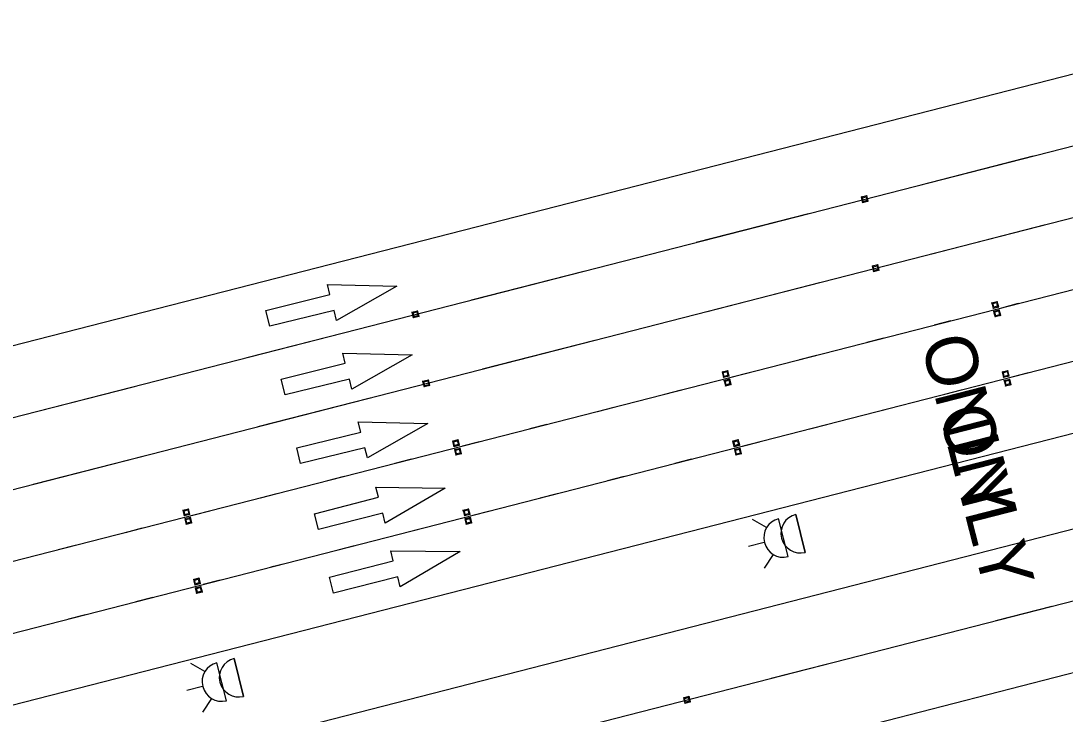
# Model space of a CAD drawing. Extents: x 2471014 to 2497726, y 6959577 to 6980268.
# Drawn here: x 2485375.6 to 2485555.7, y 6968012 to 6968131.5 of the extents above; entities that cross this region are included whole.
import ezdxf

# ---------------------------------------------------------------- set-up
doc = ezdxf.new("R2010")
doc.units = 0
for name, color, linetype in [('1', 7, 'Continuous'), ('13', 7, 'Continuous'), ('18', 7, 'Continuous'), ('23', 7, 'Continuous'), ('5', 7, 'Continuous'), ('59', 7, 'Continuous'), ('ALIGN_ML_IH35_NB_SB', 7, 'Continuous'), ('C-ANNO-NOTE', 7, 'Continuous'), ('C-COMM-IDEN', 7, 'Continuous'), ('Level 40', 7, 'Continuous'), ('p_structure fence', 7, 'Continuous'), ('RDWY_PAVE_XSTREET_FOC', 7, 'Continuous'), ('V7_25', 7, 'Continuous')]:
    doc.layers.add(name, color=color, linetype=linetype)

msp = doc.modelspace()

# ---------------------------------------------------------------- linework, layer by layer
at = {"layer": '1'}
for p, q in [((2485543.74, 6968028.09), (2485553.42, 6968030.57)), ((2485504.99, 6968018.16), (2485514.68, 6968020.64))]:
    msp.add_line(p, q, dxfattribs=at)
at = {"layer": '13'}
for p, q in [((2485091.11, 6967924.47), (2486403.87, 6968260.92)), ((2484238.76, 6967784.48), (2485861.87, 6968200.47))]:
    msp.add_line(p, q, dxfattribs=at)
at = {"layer": '18'}
for p, q in [((2485097.06, 6967901.22), (2486409.83, 6968237.67)), ((2484287.61, 6967735.06), (2485876.76, 6968142.35))]:
    msp.add_line(p, q, dxfattribs=at)
at = {"layer": '23'}
for p, q in [((2485520.51, 6968101.11), (2485521.49, 6968101.36)), ((2485520.71, 6968100.99), (2485520.51, 6968101.11)), ((2485520.51, 6968101.11), (2485520.58, 6968100.85)), ((2485520.58, 6968100.85), (2485520.76, 6968100.12)), ((2485520.88, 6968100.34), (2485520.71, 6968100.99)), ((2485521.49, 6968101.36), (2485521.37, 6968101.16)), ((2485521.37, 6968101.16), (2485521.4, 6968101.02)), ((2485521.4, 6968101.02), (2485521.54, 6968100.51)), ((2485521.74, 6968100.38), (2485521.49, 6968101.36)), ((2485521.54, 6968100.51), (2485521.74, 6968100.38)), ((2485521.74, 6968100.38), (2485520.76, 6968100.12)), ((2485520.76, 6968100.12), (2485520.88, 6968100.34)), ((2485522.38, 6968089.22), (2485523.36, 6968089.47)), ((2485522.59, 6968089.09), (2485522.38, 6968089.22)), ((2485522.38, 6968089.22), (2485522.63, 6968088.23)), ((2485522.72, 6968088.57), (2485522.59, 6968089.09)), ((2485523.61, 6968088.49), (2485522.63, 6968088.23)), ((2485522.63, 6968088.23), (2485522.75, 6968088.43)), ((2485522.75, 6968088.43), (2485522.72, 6968088.57)), ((2485523.36, 6968089.47), (2485523.24, 6968089.26)), ((2485523.24, 6968089.26), (2485523.41, 6968088.6)), ((2485523.55, 6968088.75), (2485523.36, 6968089.47)), ((2485523.41, 6968088.6), (2485523.61, 6968088.49)), ((2485523.61, 6968088.49), (2485523.55, 6968088.75)), ((2485543.01, 6968082.87), (2485543.99, 6968083.12)), ((2485543.21, 6968082.76), (2485543.01, 6968082.87)), ((2485543.01, 6968082.87), (2485543.08, 6968082.61)), ((2485543.08, 6968082.61), (2485543.26, 6968081.89)), ((2485543.38, 6968082.1), (2485543.21, 6968082.76)), ((2485543.99, 6968083.12), (2485543.87, 6968082.93)), ((2485543.87, 6968082.93), (2485543.9, 6968082.79)), ((2485543.9, 6968082.79), (2485544.04, 6968082.27)), ((2485544.24, 6968082.14), (2485543.99, 6968083.12)), ((2485443.02, 6968081.24), (2485444, 6968081.5)), ((2485443.22, 6968081.13), (2485443.02, 6968081.24)), ((2485443.02, 6968081.24), (2485443.08, 6968080.98)), ((2485443.08, 6968080.98), (2485443.27, 6968080.26)), ((2485443.39, 6968080.48), (2485443.22, 6968081.13)), ((2485444, 6968081.5), (2485443.87, 6968081.3)), ((2485443.87, 6968081.3), (2485443.91, 6968081.16)), ((2485443.91, 6968081.16), (2485444.04, 6968080.64)), ((2485444.25, 6968080.51), (2485444, 6968081.5)), ((2485444.04, 6968080.64), (2485444.25, 6968080.51)), ((2485544.24, 6968082.14), (2485543.26, 6968081.89)), ((2485543.26, 6968081.89), (2485543.38, 6968082.1)), ((2485543.34, 6968081.41), (2485544.33, 6968081.66)), ((2485543.54, 6968081.29), (2485543.34, 6968081.41)), ((2485543.34, 6968081.41), (2485543.41, 6968081.15)), ((2485543.41, 6968081.15), (2485543.59, 6968080.43)), ((2485543.71, 6968080.64), (2485543.54, 6968081.29)), ((2485544.58, 6968080.68), (2485543.59, 6968080.43)), ((2485543.59, 6968080.43), (2485543.71, 6968080.64)), ((2485544.04, 6968082.27), (2485544.24, 6968082.14)), ((2485544.33, 6968081.66), (2485544.2, 6968081.46)), ((2485544.2, 6968081.46), (2485544.24, 6968081.33)), ((2485544.24, 6968081.33), (2485544.37, 6968080.81)), ((2485544.58, 6968080.68), (2485544.33, 6968081.66)), ((2485544.37, 6968080.81), (2485544.58, 6968080.68)), ((2485444.25, 6968080.51), (2485443.27, 6968080.26)), ((2485443.27, 6968080.26), (2485443.39, 6968080.48)), ((2485496.51, 6968070.95), (2485497.5, 6968071.21)), ((2485496.72, 6968070.84), (2485496.51, 6968070.95)), ((2485496.51, 6968070.95), (2485496.58, 6968070.69)), ((2485496.58, 6968070.69), (2485496.76, 6968069.97)), ((2485496.88, 6968070.19), (2485496.72, 6968070.84)), ((2485497.75, 6968070.22), (2485496.76, 6968069.97)), ((2485496.76, 6968069.97), (2485496.88, 6968070.19)), ((2485497.5, 6968071.21), (2485497.37, 6968071.01)), ((2485497.37, 6968071.01), (2485497.41, 6968070.87)), ((2485497.41, 6968070.87), (2485497.54, 6968070.35)), ((2485497.75, 6968070.22), (2485497.5, 6968071.21)), ((2485497.54, 6968070.35), (2485497.75, 6968070.22)), ((2485544.82, 6968070.95), (2485545.81, 6968071.2)), ((2485545.03, 6968070.83), (2485544.82, 6968070.95)), ((2485544.82, 6968070.95), (2485544.89, 6968070.69)), ((2485544.89, 6968070.69), (2485545.08, 6968069.97)), ((2485545.19, 6968070.18), (2485545.03, 6968070.83)), ((2485546.06, 6968070.22), (2485545.08, 6968069.97)), ((2485545.08, 6968069.97), (2485545.19, 6968070.18)), ((2485545.81, 6968071.2), (2485545.68, 6968071)), ((2485545.68, 6968071), (2485545.72, 6968070.87)), ((2485545.72, 6968070.87), (2485545.85, 6968070.35)), ((2485546.06, 6968070.22), (2485545.81, 6968071.2)), ((2485545.85, 6968070.35), (2485546.06, 6968070.22)), ((2485444.88, 6968069.36), (2485445.87, 6968069.61)), ((2485445.09, 6968069.23), (2485444.88, 6968069.36)), ((2485444.88, 6968069.36), (2485445.13, 6968068.37)), ((2485445.22, 6968068.71), (2485445.09, 6968069.23)), ((2485446.12, 6968068.63), (2485445.13, 6968068.37)), ((2485445.13, 6968068.37), (2485445.26, 6968068.57)), ((2485445.26, 6968068.57), (2485445.22, 6968068.71)), ((2485445.87, 6968069.61), (2485445.75, 6968069.39)), ((2485445.75, 6968069.39), (2485445.92, 6968068.74)), ((2485446.05, 6968068.89), (2485445.87, 6968069.61)), ((2485445.92, 6968068.74), (2485446.12, 6968068.63)), ((2485446.12, 6968068.63), (2485446.05, 6968068.89)), ((2485496.85, 6968069.49), (2485497.83, 6968069.74)), ((2485497.05, 6968069.38), (2485496.85, 6968069.49)), ((2485496.85, 6968069.49), (2485496.91, 6968069.23)), ((2485496.91, 6968069.23), (2485497.1, 6968068.51)), ((2485497.22, 6968068.72), (2485497.05, 6968069.38)), ((2485498.08, 6968068.76), (2485497.1, 6968068.51)), ((2485497.1, 6968068.51), (2485497.22, 6968068.72)), ((2485497.83, 6968069.74), (2485497.7, 6968069.55)), ((2485497.7, 6968069.55), (2485497.74, 6968069.41)), ((2485497.74, 6968069.41), (2485497.87, 6968068.89)), ((2485498.08, 6968068.76), (2485497.83, 6968069.74)), ((2485497.87, 6968068.89), (2485498.08, 6968068.76)), ((2485545.14, 6968069.48), (2485546.13, 6968069.73)), ((2485545.35, 6968069.37), (2485545.14, 6968069.48)), ((2485545.14, 6968069.48), (2485545.21, 6968069.22)), ((2485545.21, 6968069.22), (2485545.4, 6968068.5)), ((2485545.51, 6968068.71), (2485545.35, 6968069.37)), ((2485546.38, 6968068.75), (2485545.4, 6968068.5)), ((2485545.4, 6968068.5), (2485545.51, 6968068.71)), ((2485546.13, 6968069.73), (2485546, 6968069.54)), ((2485546, 6968069.54), (2485546.04, 6968069.4)), ((2485546.04, 6968069.4), (2485546.17, 6968068.88)), ((2485546.38, 6968068.75), (2485546.13, 6968069.73)), ((2485546.17, 6968068.88), (2485546.38, 6968068.75)), ((2485450.02, 6968059.04), (2485451, 6968059.29)), ((2485450.22, 6968058.92), (2485450.02, 6968059.04)), ((2485450.02, 6968059.04), (2485450.08, 6968058.78)), ((2485451, 6968059.29), (2485450.87, 6968059.09)), ((2485450.87, 6968059.09), (2485450.91, 6968058.96)), ((2485451.25, 6968058.31), (2485451, 6968059.29)), ((2485498.33, 6968059.03), (2485499.31, 6968059.28)), ((2485498.53, 6968058.92), (2485498.33, 6968059.03)), ((2485498.33, 6968059.03), (2485498.39, 6968058.77)), ((2485499.31, 6968059.28), (2485499.18, 6968059.09)), ((2485499.18, 6968059.09), (2485499.22, 6968058.95)), ((2485499.56, 6968058.3), (2485499.31, 6968059.28)), ((2485450.08, 6968058.78), (2485450.27, 6968058.06)), ((2485450.39, 6968058.27), (2485450.22, 6968058.92)), ((2485451.25, 6968058.31), (2485450.27, 6968058.06)), ((2485450.27, 6968058.06), (2485450.39, 6968058.27)), ((2485450.35, 6968057.57), (2485451.33, 6968057.83)), ((2485450.55, 6968057.46), (2485450.35, 6968057.57)), ((2485450.35, 6968057.57), (2485450.41, 6968057.31)), ((2485450.41, 6968057.31), (2485450.6, 6968056.59)), ((2485450.72, 6968056.81), (2485450.55, 6968057.46)), ((2485450.91, 6968058.96), (2485451.04, 6968058.44)), ((2485451.04, 6968058.44), (2485451.25, 6968058.31)), ((2485451.33, 6968057.83), (2485451.21, 6968057.63)), ((2485451.21, 6968057.63), (2485451.24, 6968057.49)), ((2485451.24, 6968057.49), (2485451.37, 6968056.97)), ((2485451.58, 6968056.84), (2485451.33, 6968057.83)), ((2485498.39, 6968058.77), (2485498.58, 6968058.05)), ((2485498.7, 6968058.26), (2485498.53, 6968058.92)), ((2485499.56, 6968058.3), (2485498.58, 6968058.05)), ((2485498.58, 6968058.05), (2485498.7, 6968058.26)), ((2485498.65, 6968057.56), (2485499.63, 6968057.82)), ((2485498.85, 6968057.45), (2485498.65, 6968057.56)), ((2485498.65, 6968057.56), (2485498.71, 6968057.3)), ((2485498.71, 6968057.3), (2485498.9, 6968056.58)), ((2485499.02, 6968056.8), (2485498.85, 6968057.45)), ((2485499.22, 6968058.95), (2485499.35, 6968058.43)), ((2485499.35, 6968058.43), (2485499.56, 6968058.3)), ((2485499.63, 6968057.82), (2485499.5, 6968057.62)), ((2485499.5, 6968057.62), (2485499.54, 6968057.48)), ((2485499.54, 6968057.48), (2485499.67, 6968056.96)), ((2485499.88, 6968056.83), (2485499.63, 6968057.82)), ((2485451.58, 6968056.84), (2485450.6, 6968056.59)), ((2485450.6, 6968056.59), (2485450.72, 6968056.81)), ((2485451.37, 6968056.97), (2485451.58, 6968056.84)), ((2485499.88, 6968056.83), (2485498.9, 6968056.58)), ((2485498.9, 6968056.58), (2485499.02, 6968056.8)), ((2485499.67, 6968056.96), (2485499.88, 6968056.83)), ((2485403.52, 6968047.12), (2485404.5, 6968047.37)), ((2485403.72, 6968047.01), (2485403.52, 6968047.12)), ((2485403.52, 6968047.12), (2485403.59, 6968046.86)), ((2485403.59, 6968046.86), (2485403.77, 6968046.14)), ((2485403.89, 6968046.35), (2485403.72, 6968047.01)), ((2485404.5, 6968047.37), (2485404.38, 6968047.18)), ((2485404.38, 6968047.18), (2485404.41, 6968047.04)), ((2485404.41, 6968047.04), (2485404.55, 6968046.52)), ((2485404.75, 6968046.39), (2485404.5, 6968047.37)), ((2485404.55, 6968046.52), (2485404.75, 6968046.39)), ((2485451.83, 6968047.11), (2485452.81, 6968047.37)), ((2485452.03, 6968047), (2485451.83, 6968047.11)), ((2485451.83, 6968047.11), (2485451.9, 6968046.85)), ((2485451.9, 6968046.85), (2485452.08, 6968046.13)), ((2485452.2, 6968046.35), (2485452.03, 6968047)), ((2485452.81, 6968047.37), (2485452.69, 6968047.17)), ((2485452.69, 6968047.17), (2485452.72, 6968047.03)), ((2485452.72, 6968047.03), (2485452.85, 6968046.51)), ((2485453.06, 6968046.38), (2485452.81, 6968047.37)), ((2485452.85, 6968046.51), (2485453.06, 6968046.38)), ((2485404.75, 6968046.39), (2485403.77, 6968046.14)), ((2485403.77, 6968046.14), (2485403.89, 6968046.35)), ((2485403.85, 6968045.66), (2485404.83, 6968045.91)), ((2485404.05, 6968045.54), (2485403.85, 6968045.66)), ((2485403.85, 6968045.66), (2485403.92, 6968045.4)), ((2485403.92, 6968045.4), (2485404.1, 6968044.68)), ((2485404.22, 6968044.89), (2485404.05, 6968045.54)), ((2485405.08, 6968044.93), (2485404.1, 6968044.68)), ((2485404.1, 6968044.68), (2485404.22, 6968044.89)), ((2485404.83, 6968045.91), (2485404.71, 6968045.71)), ((2485404.71, 6968045.71), (2485404.74, 6968045.58)), ((2485404.74, 6968045.58), (2485404.88, 6968045.06)), ((2485405.08, 6968044.93), (2485404.83, 6968045.91)), ((2485404.88, 6968045.06), (2485405.08, 6968044.93)), ((2485453.06, 6968046.38), (2485452.08, 6968046.13)), ((2485452.08, 6968046.13), (2485452.2, 6968046.35)), ((2485452.15, 6968045.65), (2485453.13, 6968045.9)), ((2485452.35, 6968045.53), (2485452.15, 6968045.65)), ((2485452.15, 6968045.65), (2485452.22, 6968045.39)), ((2485452.22, 6968045.39), (2485452.4, 6968044.67)), ((2485452.52, 6968044.88), (2485452.35, 6968045.53)), ((2485453.38, 6968044.92), (2485452.4, 6968044.67)), ((2485452.4, 6968044.67), (2485452.52, 6968044.88)), ((2485453.13, 6968045.9), (2485453.01, 6968045.7)), ((2485453.01, 6968045.7), (2485453.04, 6968045.57)), ((2485453.04, 6968045.57), (2485453.17, 6968045.05)), ((2485453.38, 6968044.92), (2485453.13, 6968045.9)), ((2485453.17, 6968045.05), (2485453.38, 6968044.92)), ((2485405.33, 6968035.2), (2485406.32, 6968035.45)), ((2485405.53, 6968035.08), (2485405.33, 6968035.2)), ((2485405.33, 6968035.2), (2485405.4, 6968034.94)), ((2485405.4, 6968034.94), (2485405.58, 6968034.22)), ((2485405.7, 6968034.43), (2485405.53, 6968035.08)), ((2485406.57, 6968034.47), (2485405.58, 6968034.22)), ((2485405.58, 6968034.22), (2485405.7, 6968034.43)), ((2485405.65, 6968033.73), (2485406.63, 6968033.98)), ((2485406.32, 6968035.45), (2485406.19, 6968035.25)), ((2485406.19, 6968035.25), (2485406.22, 6968035.12)), ((2485406.22, 6968035.12), (2485406.36, 6968034.6)), ((2485406.57, 6968034.47), (2485406.32, 6968035.45)), ((2485406.36, 6968034.6), (2485406.57, 6968034.47)), ((2485406.63, 6968033.98), (2485406.51, 6968033.79)), ((2485406.88, 6968033), (2485406.63, 6968033.98)), ((2485405.85, 6968033.62), (2485405.65, 6968033.73)), ((2485405.65, 6968033.73), (2485405.72, 6968033.47)), ((2485405.72, 6968033.47), (2485405.9, 6968032.75)), ((2485406.02, 6968032.96), (2485405.85, 6968033.62)), ((2485406.88, 6968033), (2485405.9, 6968032.75)), ((2485405.9, 6968032.75), (2485406.02, 6968032.96)), ((2485406.51, 6968033.79), (2485406.54, 6968033.65)), ((2485406.54, 6968033.65), (2485406.68, 6968033.13)), ((2485406.68, 6968033.13), (2485406.88, 6968033)), ((2485489.84, 6968014.79), (2485490.83, 6968015.04)), ((2485490.05, 6968014.68), (2485489.84, 6968014.79)), ((2485489.84, 6968014.79), (2485489.91, 6968014.53)), ((2485489.91, 6968014.53), (2485490.1, 6968013.81)), ((2485490.21, 6968014.02), (2485490.05, 6968014.68)), ((2485491.08, 6968014.06), (2485490.1, 6968013.81)), ((2485490.1, 6968013.81), (2485490.21, 6968014.02)), ((2485490.83, 6968015.04), (2485490.7, 6968014.85)), ((2485490.7, 6968014.85), (2485490.74, 6968014.71)), ((2485490.74, 6968014.71), (2485490.87, 6968014.19)), ((2485491.08, 6968014.06), (2485490.83, 6968015.04)), ((2485490.87, 6968014.19), (2485491.08, 6968014.06))]:
    msp.add_line(p, q, dxfattribs=at)
for points in [[(2485520.71, 6968100.99), (2485521.37, 6968101.16), (2485521.54, 6968100.51), (2485520.88, 6968100.34)], [(2485523.41, 6968088.6), (2485522.75, 6968088.43), (2485522.59, 6968089.09), (2485523.24, 6968089.26)], [(2485543.21, 6968082.76), (2485543.87, 6968082.93), (2485544.04, 6968082.27), (2485543.38, 6968082.1)], [(2485443.22, 6968081.13), (2485443.87, 6968081.3), (2485444.04, 6968080.64), (2485443.39, 6968080.48)], [(2485543.54, 6968081.29), (2485544.2, 6968081.46), (2485544.37, 6968080.81), (2485543.71, 6968080.64)], [(2485496.72, 6968070.84), (2485497.37, 6968071.01), (2485497.54, 6968070.35), (2485496.88, 6968070.19)], [(2485545.03, 6968070.83), (2485545.68, 6968071), (2485545.85, 6968070.35), (2485545.19, 6968070.18)], [(2485445.92, 6968068.74), (2485445.26, 6968068.57), (2485445.09, 6968069.23), (2485445.75, 6968069.39)], [(2485497.05, 6968069.38), (2485497.7, 6968069.55), (2485497.87, 6968068.89), (2485497.22, 6968068.72)], [(2485545.35, 6968069.37), (2485546, 6968069.54), (2485546.17, 6968068.88), (2485545.51, 6968068.71)], [(2485450.22, 6968058.92), (2485450.87, 6968059.09), (2485451.04, 6968058.44), (2485450.39, 6968058.27)], [(2485498.53, 6968058.92), (2485499.18, 6968059.09), (2485499.35, 6968058.43), (2485498.7, 6968058.26)], [(2485450.55, 6968057.46), (2485451.21, 6968057.63), (2485451.37, 6968056.97), (2485450.72, 6968056.81)], [(2485498.85, 6968057.45), (2485499.5, 6968057.62), (2485499.67, 6968056.96), (2485499.02, 6968056.8)], [(2485403.72, 6968047.01), (2485404.38, 6968047.18), (2485404.55, 6968046.52), (2485403.89, 6968046.35)], [(2485452.03, 6968047), (2485452.69, 6968047.17), (2485452.85, 6968046.51), (2485452.2, 6968046.35)], [(2485404.05, 6968045.54), (2485404.71, 6968045.71), (2485404.88, 6968045.06), (2485404.22, 6968044.89)], [(2485452.35, 6968045.53), (2485453.01, 6968045.7), (2485453.17, 6968045.05), (2485452.52, 6968044.88)], [(2485405.53, 6968035.08), (2485406.19, 6968035.25), (2485406.36, 6968034.6), (2485405.7, 6968034.43)], [(2485405.85, 6968033.62), (2485406.51, 6968033.79), (2485406.68, 6968033.13), (2485406.02, 6968032.96)], [(2485490.05, 6968014.68), (2485490.7, 6968014.85), (2485490.87, 6968014.19), (2485490.21, 6968014.02)]]:
    msp.add_lwpolyline(points, close=True, dxfattribs=at)
at = {"layer": '5'}
msp.add_arc((2479474.04, 6969335.88), 8460, 6.37617, 6.37617, dxfattribs=at)
at = {"layer": '59'}
for p, q in [((2484247.64, 6967749.59), (2485580.2, 6968091.11)), ((2484442.23, 6967787.08), (2485583.18, 6968079.49))]:
    msp.add_line(p, q, dxfattribs=at)
at = {"layer": 'ALIGN_ML_IH35_NB_SB'}
for p, q in [((2485428.87, 6968084.28), (2485428.44, 6968086.03)), ((2485428.44, 6968086.03), (2485440.43, 6968085.76)), ((2485417.82, 6968081.57), (2485428.87, 6968084.28)), ((2485440.43, 6968085.76), (2485430.02, 6968079.81)), ((2485418.5, 6968078.83), (2485417.82, 6968081.57)), ((2485429.6, 6968081.56), (2485418.5, 6968078.83)), ((2485430.02, 6968079.81), (2485429.6, 6968081.56)), ((2485431.53, 6968072.44), (2485431.1, 6968074.19)), ((2485431.1, 6968074.19), (2485443.09, 6968073.92)), ((2485443.09, 6968073.92), (2485432.69, 6968067.96)), ((2485420.48, 6968069.73), (2485431.53, 6968072.44)), ((2485421.16, 6968066.99), (2485420.48, 6968069.73)), ((2485432.26, 6968069.71), (2485421.16, 6968066.99)), ((2485432.69, 6968067.96), (2485432.26, 6968069.71)), ((2485434.19, 6968060.59), (2485433.76, 6968062.34)), ((2485433.76, 6968062.34), (2485445.75, 6968062.07)), ((2485445.75, 6968062.07), (2485435.35, 6968056.12)), ((2485423.15, 6968057.88), (2485434.19, 6968060.59)), ((2485423.82, 6968055.14), (2485423.15, 6968057.88)), ((2485434.92, 6968057.87), (2485423.82, 6968055.14)), ((2485435.35, 6968056.12), (2485434.92, 6968057.87)), ((2485437.24, 6968049.34), (2485436.79, 6968051.08)), ((2485436.79, 6968051.08), (2485448.78, 6968050.93)), ((2485448.78, 6968050.93), (2485438.44, 6968044.88)), ((2485426.22, 6968046.51), (2485437.24, 6968049.34)), ((2485426.92, 6968043.78), (2485426.22, 6968046.51)), ((2485438, 6968046.62), (2485426.92, 6968043.78)), ((2485438.44, 6968044.88), (2485438, 6968046.62)), ((2485439.82, 6968038.37), (2485439.37, 6968040.12)), ((2485439.37, 6968040.12), (2485451.36, 6968039.97)), ((2485451.36, 6968039.97), (2485441.02, 6968033.91)), ((2485428.81, 6968035.55), (2485439.82, 6968038.37)), ((2485440.58, 6968035.66), (2485429.51, 6968032.82)), ((2485441.02, 6968033.91), (2485440.58, 6968035.66)), ((2485429.51, 6968032.82), (2485428.81, 6968035.55))]:
    msp.add_line(p, q, dxfattribs=at)
at = {"layer": 'C-ANNO-NOTE'}
msp.add_line((2485094.03, 6967912.83), (2486406.85, 6968249.3), dxfattribs=at)
at = {"layer": 'C-COMM-IDEN'}
for p, q in [((2485504.18, 6968044.12), (2485501.75, 6968045.53)), ((2485507.89, 6968039.11), (2485506.26, 6968045.66)), ((2485509.22, 6968046.4), (2485510.86, 6968039.85)), ((2485510.86, 6968039.85), (2485509.22, 6968046.4)), ((2485503.8, 6968041.56), (2485501.07, 6968040.88)), ((2485505.34, 6968039.49), (2485503.8, 6968037.13)), ((2485412.36, 6968021.57), (2485413.99, 6968015.02)), ((2485413.99, 6968015.02), (2485412.36, 6968021.57)), ((2485407.31, 6968019.29), (2485404.88, 6968020.71)), ((2485411.03, 6968014.28), (2485409.39, 6968020.83)), ((2485406.93, 6968016.74), (2485404.2, 6968016.06)), ((2485408.47, 6968014.66), (2485406.93, 6968012.31))]:
    msp.add_line(p, q, dxfattribs=at)
for centre in [(2485507.08, 6968042.38), (2485510.04, 6968043.12), (2485413.17, 6968018.29), (2485410.21, 6968017.55)]:
    msp.add_arc(centre, 3.37, 104.0161, 284.0161, dxfattribs=at)
at = {"layer": 'Level 40'}
for p, q in [((2485544.76, 6968082.03), (2485547.66, 6968082.78)), ((2485533.13, 6968079.05), (2485536.04, 6968079.8)), ((2485521.51, 6968076.07), (2485524.41, 6968076.82)), ((2485509.88, 6968073.09), (2485512.79, 6968073.84)), ((2485498.26, 6968070.11), (2485501.17, 6968070.86)), ((2485546.54, 6968070.1), (2485549.45, 6968070.84)), ((2485486.64, 6968067.13), (2485489.54, 6968067.88)), ((2485534.92, 6968067.12), (2485537.82, 6968067.87)), ((2485475.01, 6968064.16), (2485477.92, 6968064.9)), ((2485523.29, 6968064.14), (2485526.2, 6968064.89)), ((2485463.39, 6968061.18), (2485466.29, 6968061.92)), ((2485511.67, 6968061.16), (2485514.57, 6968061.91)), ((2485451.76, 6968058.2), (2485454.67, 6968058.94)), ((2485500.04, 6968058.18), (2485502.95, 6968058.93)), ((2485440.14, 6968055.22), (2485443.04, 6968055.96)), ((2485488.42, 6968055.2), (2485491.32, 6968055.95)), ((2485428.51, 6968052.24), (2485431.42, 6968052.98)), ((2485476.79, 6968052.23), (2485479.7, 6968052.97)), ((2485416.89, 6968049.26), (2485419.8, 6968050)), ((2485465.17, 6968049.25), (2485468.08, 6968049.99)), ((2485405.27, 6968046.28), (2485408.17, 6968047.03)), ((2485453.55, 6968046.27), (2485456.45, 6968047.01)), ((2485393.64, 6968043.3), (2485396.55, 6968044.05)), ((2485441.92, 6968043.29), (2485444.83, 6968044.03)), ((2485382.02, 6968040.32), (2485384.92, 6968041.07)), ((2485430.3, 6968040.31), (2485433.2, 6968041.05)), ((2485418.67, 6968037.33), (2485421.58, 6968038.07)), ((2485407.05, 6968034.35), (2485409.95, 6968035.09)), ((2485395.42, 6968031.37), (2485398.33, 6968032.12)), ((2485383.8, 6968028.39), (2485386.71, 6968029.14))]:
    msp.add_line(p, q, dxfattribs=at)
at = {"layer": 'RDWY_PAVE_XSTREET_FOC'}
for p, q in [((2485530.8, 6968103.23), (2485550.17, 6968108.19)), ((2485492.05, 6968093.3), (2485511.42, 6968098.26)), ((2485532.69, 6968091.32), (2485552.06, 6968096.29)), ((2485453.3, 6968083.37), (2485472.67, 6968088.33)), ((2485493.94, 6968081.39), (2485513.31, 6968086.36)), ((2485414.55, 6968073.44), (2485433.93, 6968078.4)), ((2485455.19, 6968071.46), (2485474.56, 6968076.43)), ((2485375.81, 6968063.51), (2485395.18, 6968068.47)), ((2485416.44, 6968061.53), (2485435.82, 6968066.5)), ((2485377.69, 6968051.6), (2485397.07, 6968056.57))]:
    msp.add_line(p, q, dxfattribs=at)
at = {"layer": 'V7_25'}
for p, q in [((2484241.91, 6967772.9), (2485864.85, 6968188.84)), ((2484244.68, 6967761.22), (2485577.22, 6968102.74))]:
    msp.add_line(p, q, dxfattribs=at)

# ---------------------------------------------------------------- texts
at = {"layer": 'p_structure fence'}
for p in [(2485530.75, 6968076.23), (2485533.84, 6968064.17)]:
    msp.add_text('ONLY', height=8.898, rotation=284.3716, dxfattribs=at).set_placement(p)

doc.saveas('drawing.dxf')
